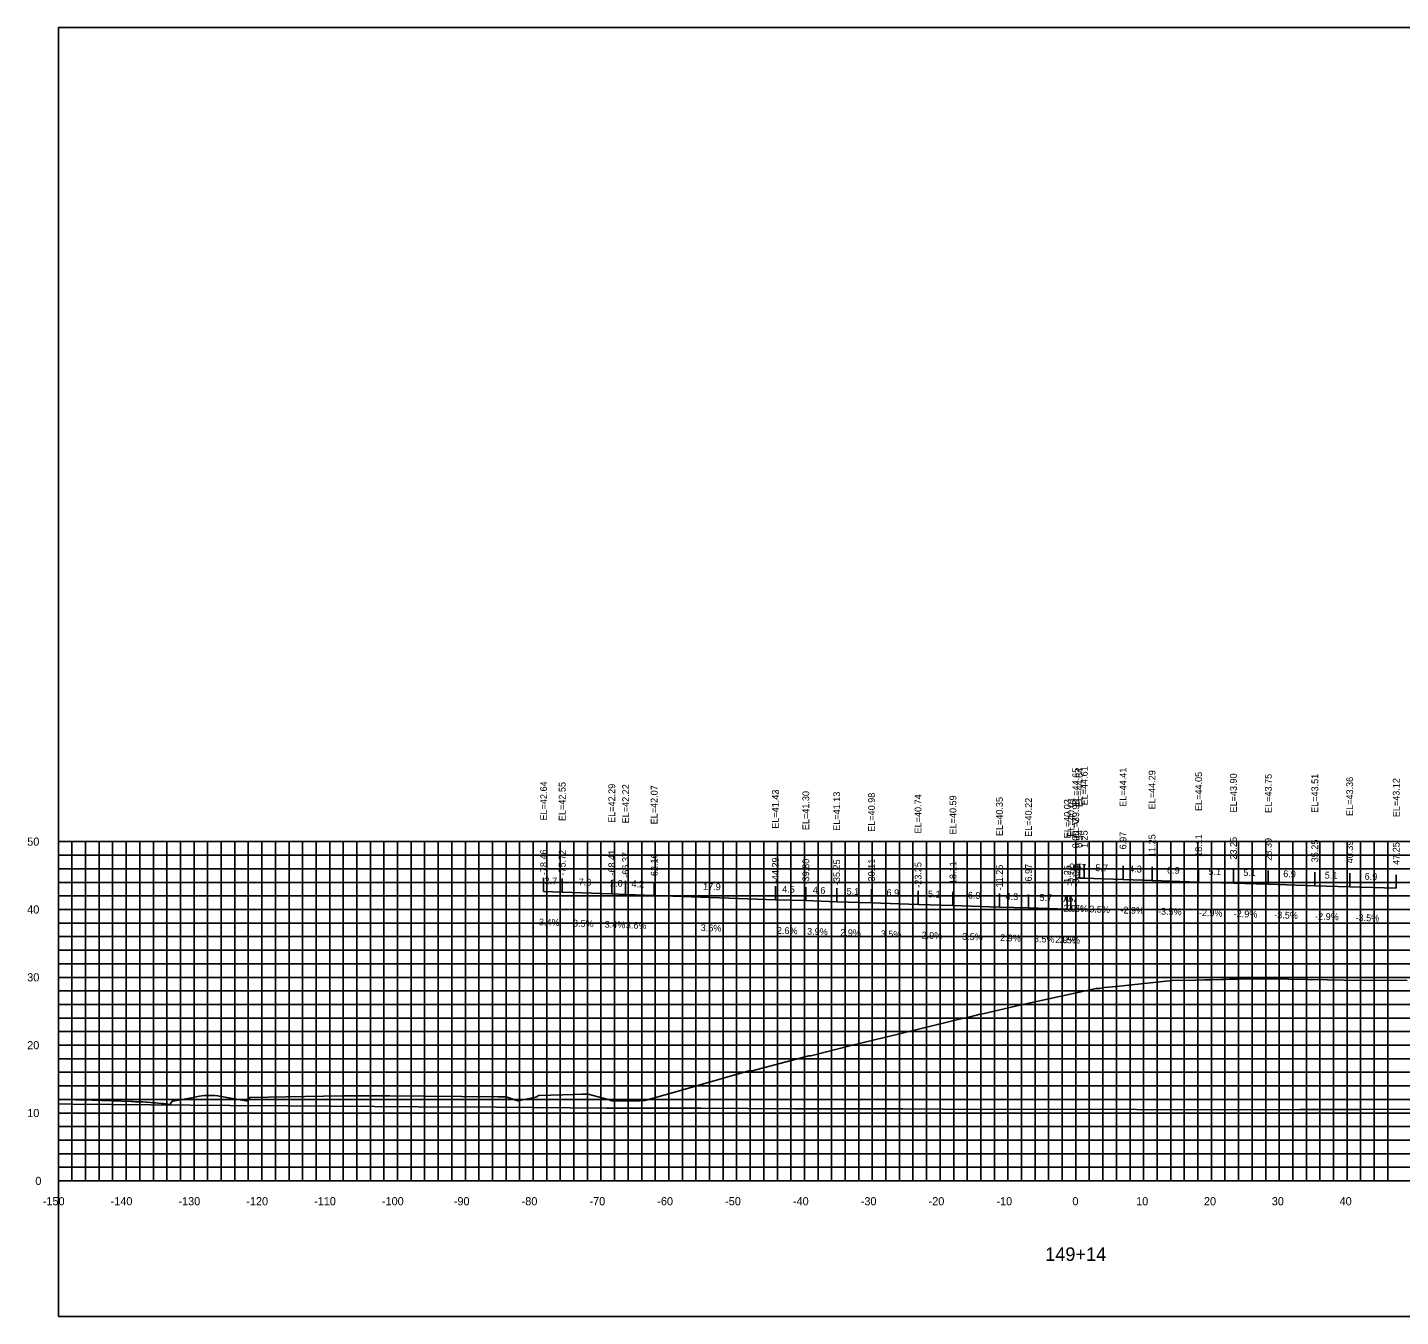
# Model space of a CAD drawing. Extents: x 1800880 to 1818864, y 245271 to 250560.
# Drawn here: x 1810016.6 to 1810219, y 249144.9 to 249334.9 of the extents above; entities that cross this region are included whole.
import ezdxf

# ---------------------------------------------------------------- set-up
doc = ezdxf.new("R2010")
doc.units = 0
for name, color, linetype in [('33', 7, 'Continuous'), ('ANNO-TXT', 7, 'Continuous'), ('AXIS', 7, 'Continuous'), ('CL-CNST', 7, 'Continuous'), ('DESIGN - DRAINAGE - Bridges', 7, 'Continuous'), ('Level 32', 7, 'Continuous'), ('Level 37', 7, 'Continuous'), ('Level 46', 7, 'Continuous'), ('Level 62', 7, 'Continuous'), ('SHT-BDR', 7, 'Continuous')]:
    doc.layers.add(name, color=color, linetype=linetype)

msp = doc.modelspace()

# ---------------------------------------------------------------- linework, layer by layer
at = {"layer": 'AXIS'}
msp.add_lwpolyline([(1810171.13, 249209.56), (1810171.67, 249209.54), (1810172.38, 249209.52), (1810178.1, 249209.32), (1810182.38, 249209.19), (1810189.25, 249208.95), (1810194.38, 249208.8), (1810199.52, 249208.65), (1810206.38, 249208.41), (1810211.52, 249208.26), (1810218.38, 249208.02)], dxfattribs=at)
at = {"layer": 'CL-CNST'}
msp.add_lwpolyline([(1810021.13, 249176.87), (1810026.09, 249176.8), (1810031.88, 249176.59), (1810032.15, 249176.58), (1810032.44, 249176.57), (1810032.77, 249176.56), (1810033.13, 249176.55), (1810033.54, 249176.53), (1810034, 249176.52), (1810034.22, 249176.51), (1810035.25, 249176.39), (1810035.47, 249176.39), (1810036.28, 249176.31), (1810036.63, 249176.28), (1810037.55, 249176.18), (1810037.6, 249176.18), (1810037.65, 249176.12), (1810037.68, 249176.29), (1810037.91, 249176.66), (1810038.02, 249176.66), (1810040.73, 249177.15), (1810041.91, 249177.37), (1810042.61, 249177.47), (1810042.7, 249177.48), (1810042.92, 249177.48), (1810043.49, 249177.49), (1810043.68, 249177.5), (1810043.88, 249177.5), (1810044.01, 249177.5), (1810044.19, 249177.5), (1810044.59, 249177.44), (1810049.07, 249176.65), (1810049.18, 249176.89), (1810049.26, 249177.06), (1810049.34, 249177.2), (1810054.69, 249177.3), (1810062.99, 249177.44), (1810070.01, 249177.41), (1810075.25, 249177.4), (1810085.99, 249177.29), (1810087.25, 249177.28), (1810087.29, 249177.26), (1810088.89, 249176.71), (1810091.52, 249177.22), (1810091.98, 249177.47), (1810091.98, 249177.47), (1810097.26, 249177.65), (1810098.3, 249177.69), (1810098.72, 249177.7), (1810099.2, 249177.7), (1810099.24, 249177.7), (1810102.21, 249176.89), (1810102.72, 249176.71), (1810102.78, 249176.71), (1810103.22, 249176.7), (1810103.74, 249176.69), (1810103.87, 249176.69), (1810106.83, 249176.68), (1810107.4, 249176.76), (1810107.6, 249176.76), (1810111.49, 249177.83), (1810122.95, 249181.12), (1810123.16, 249181.12), (1810123.42, 249181.12), (1810131.79, 249183.32), (1810132.09, 249183.33), (1810138.03, 249184.83), (1810142.9, 249186.04), (1810143.12, 249186.09), (1810154.58, 249188.87), (1810154.82, 249188.88), (1810157.02, 249189.49), (1810157.41, 249189.51), (1810162.88, 249190.79), (1810174.12, 249193.25), (1810174.16, 249193.25), (1810174.64, 249193.25), (1810175.37, 249193.39), (1810177.07, 249193.54), (1810179.38, 249193.78), (1810185.33, 249194.41), (1810188.78, 249194.5), (1810190.15, 249194.53), (1810190.59, 249194.55), (1810191.08, 249194.55), (1810192.68, 249194.59), (1810193.15, 249194.6), (1810193.78, 249194.62), (1810195.17, 249194.65), (1810197.09, 249194.7), (1810199.54, 249194.66), (1810208.26, 249194.53), (1810210.69, 249194.5), (1810219.98, 249194.41)], dxfattribs=at)
at = {"layer": 'DESIGN - DRAINAGE - Bridges'}
for p, q in [((1810021.07, 249214.9), (1810021.13, 249214.9)), ((1810021.13, 249164.9), (1810021.13, 249214.9)), ((1810021.07, 249204.9), (1810021.13, 249204.9)), ((1810021.07, 249194.9), (1810021.13, 249194.9)), ((1810021.07, 249184.9), (1810021.13, 249184.9)), ((1810021.07, 249174.9), (1810021.13, 249174.9)), ((1810021.07, 249164.9), (1810021.13, 249164.9)), ((1810021.13, 249164.9), (1810321.13, 249164.9)), ((1810021.13, 249164.84), (1810021.13, 249164.9)), ((1810031.13, 249164.84), (1810031.13, 249164.9)), ((1810041.13, 249164.84), (1810041.13, 249164.9)), ((1810051.13, 249164.84), (1810051.13, 249164.9)), ((1810061.13, 249164.84), (1810061.13, 249164.9)), ((1810071.13, 249164.84), (1810071.13, 249164.9)), ((1810081.13, 249164.84), (1810081.13, 249164.9)), ((1810091.13, 249164.84), (1810091.13, 249164.9)), ((1810101.13, 249164.84), (1810101.13, 249164.9)), ((1810111.13, 249164.84), (1810111.13, 249164.9)), ((1810121.13, 249164.84), (1810121.13, 249164.9)), ((1810131.13, 249164.84), (1810131.13, 249164.9)), ((1810141.13, 249164.84), (1810141.13, 249164.9)), ((1810151.13, 249164.84), (1810151.13, 249164.9)), ((1810161.13, 249164.84), (1810161.13, 249164.9)), ((1810171.13, 249164.84), (1810171.13, 249164.9)), ((1810181.13, 249164.84), (1810181.13, 249164.9)), ((1810191.13, 249164.84), (1810191.13, 249164.9)), ((1810201.13, 249164.84), (1810201.13, 249164.9)), ((1810211.13, 249164.84), (1810211.13, 249164.9))]:
    msp.add_line(p, q, dxfattribs=at)
at = {"layer": 'Level 37'}
for p, q in [((1810171.13, 249209.56), (1810171.13, 249211.56)), ((1810171.67, 249209.54), (1810171.67, 249211.54)), ((1810172.38, 249209.52), (1810172.38, 249211.52)), ((1810178.1, 249209.32), (1810178.1, 249211.32)), ((1810182.38, 249209.19), (1810182.38, 249211.19)), ((1810189.25, 249208.95), (1810189.25, 249210.95)), ((1810194.38, 249208.8), (1810194.38, 249210.8)), ((1810199.52, 249208.65), (1810199.52, 249210.65)), ((1810206.38, 249208.41), (1810206.38, 249210.41)), ((1810211.52, 249208.26), (1810211.52, 249210.26)), ((1810092.67, 249207.55), (1810092.67, 249209.55)), ((1810095.41, 249207.45), (1810095.41, 249209.45)), ((1810102.72, 249207.2), (1810102.72, 249209.2)), ((1810104.76, 249207.13), (1810104.76, 249209.13)), ((1810108.97, 249206.98), (1810108.97, 249208.98)), ((1810126.84, 249206.33), (1810126.84, 249208.33)), ((1810126.84, 249206.32), (1810126.84, 249208.32)), ((1810131.33, 249206.21), (1810131.33, 249208.21)), ((1810135.88, 249206.03), (1810135.88, 249208.03)), ((1810218.38, 249208.02), (1810218.38, 249210.02)), ((1810141.02, 249205.88), (1810141.02, 249207.88)), ((1810147.88, 249205.64), (1810147.88, 249207.64)), ((1810153.02, 249205.49), (1810153.02, 249207.49)), ((1810159.88, 249205.25), (1810159.88, 249207.25)), ((1810164.16, 249205.13), (1810164.16, 249207.13)), ((1810169.88, 249204.93), (1810169.88, 249206.93)), ((1810170.42, 249204.91), (1810170.42, 249206.91)), ((1810171.13, 249204.89), (1810171.13, 249206.89))]:
    msp.add_line(p, q, dxfattribs=at)
msp.add_lwpolyline([(1810021.13, 249144.9), (1810321.13, 249144.9), (1810321.13, 249334.9), (1810021.13, 249334.9)], close=True, dxfattribs=at)
at = {"layer": 'Level 46'}
for p, q in [((1810021.13, 249214.9), (1810321.13, 249214.9)), ((1810021.13, 249164.9), (1810021.13, 249214.9)), ((1810023.13, 249164.9), (1810023.13, 249214.9)), ((1810025.13, 249164.9), (1810025.13, 249214.9)), ((1810027.13, 249164.9), (1810027.13, 249214.9)), ((1810029.13, 249164.9), (1810029.13, 249214.9)), ((1810031.13, 249164.9), (1810031.13, 249214.9)), ((1810033.13, 249164.9), (1810033.13, 249214.9)), ((1810035.13, 249164.9), (1810035.13, 249214.9)), ((1810037.13, 249164.9), (1810037.13, 249214.9)), ((1810039.13, 249164.9), (1810039.13, 249214.9)), ((1810041.13, 249164.9), (1810041.13, 249214.9)), ((1810043.13, 249164.9), (1810043.13, 249214.9)), ((1810045.13, 249164.9), (1810045.13, 249214.9)), ((1810047.13, 249164.9), (1810047.13, 249214.9)), ((1810049.13, 249164.9), (1810049.13, 249214.9)), ((1810051.13, 249164.9), (1810051.13, 249214.9)), ((1810053.13, 249164.9), (1810053.13, 249214.9)), ((1810055.13, 249164.9), (1810055.13, 249214.9)), ((1810057.13, 249164.9), (1810057.13, 249214.9)), ((1810059.13, 249164.9), (1810059.13, 249214.9)), ((1810061.13, 249164.9), (1810061.13, 249214.9)), ((1810063.13, 249164.9), (1810063.13, 249214.9)), ((1810065.13, 249164.9), (1810065.13, 249214.9)), ((1810067.13, 249164.9), (1810067.13, 249214.9)), ((1810069.13, 249164.9), (1810069.13, 249214.9)), ((1810071.13, 249164.9), (1810071.13, 249214.9)), ((1810073.13, 249164.9), (1810073.13, 249214.9)), ((1810075.13, 249164.9), (1810075.13, 249214.9)), ((1810077.13, 249164.9), (1810077.13, 249214.9)), ((1810079.13, 249164.9), (1810079.13, 249214.9)), ((1810081.13, 249164.9), (1810081.13, 249214.9)), ((1810083.13, 249164.9), (1810083.13, 249214.9)), ((1810085.13, 249164.9), (1810085.13, 249214.9)), ((1810087.13, 249164.9), (1810087.13, 249214.9)), ((1810089.13, 249164.9), (1810089.13, 249214.9)), ((1810091.13, 249164.9), (1810091.13, 249214.9)), ((1810093.13, 249164.9), (1810093.13, 249214.9)), ((1810095.13, 249164.9), (1810095.13, 249214.9)), ((1810097.13, 249164.9), (1810097.13, 249214.9)), ((1810099.13, 249164.9), (1810099.13, 249214.9)), ((1810101.13, 249164.9), (1810101.13, 249214.9)), ((1810103.13, 249164.9), (1810103.13, 249214.9)), ((1810105.13, 249164.9), (1810105.13, 249214.9)), ((1810107.13, 249164.9), (1810107.13, 249214.9)), ((1810109.13, 249164.9), (1810109.13, 249214.9)), ((1810111.13, 249164.9), (1810111.13, 249214.9)), ((1810113.13, 249164.9), (1810113.13, 249214.9)), ((1810115.13, 249164.9), (1810115.13, 249214.9)), ((1810117.13, 249164.9), (1810117.13, 249214.9)), ((1810119.13, 249164.9), (1810119.13, 249214.9)), ((1810121.13, 249164.9), (1810121.13, 249214.9)), ((1810123.13, 249164.9), (1810123.13, 249214.9)), ((1810125.13, 249164.9), (1810125.13, 249214.9)), ((1810127.13, 249164.9), (1810127.13, 249214.9)), ((1810129.13, 249164.9), (1810129.13, 249214.9)), ((1810131.13, 249164.9), (1810131.13, 249214.9)), ((1810133.13, 249164.9), (1810133.13, 249214.9)), ((1810135.13, 249164.9), (1810135.13, 249214.9)), ((1810137.13, 249164.9), (1810137.13, 249214.9)), ((1810139.13, 249164.9), (1810139.13, 249214.9)), ((1810141.13, 249164.9), (1810141.13, 249214.9)), ((1810143.13, 249164.9), (1810143.13, 249214.9)), ((1810145.13, 249164.9), (1810145.13, 249214.9)), ((1810147.13, 249164.9), (1810147.13, 249214.9)), ((1810149.13, 249164.9), (1810149.13, 249214.9)), ((1810151.13, 249164.9), (1810151.13, 249214.9)), ((1810153.13, 249164.9), (1810153.13, 249214.9)), ((1810155.13, 249164.9), (1810155.13, 249214.9)), ((1810157.13, 249164.9), (1810157.13, 249214.9)), ((1810159.13, 249164.9), (1810159.13, 249214.9)), ((1810161.13, 249164.9), (1810161.13, 249214.9)), ((1810163.13, 249164.9), (1810163.13, 249214.9)), ((1810165.13, 249164.9), (1810165.13, 249214.9)), ((1810167.13, 249164.9), (1810167.13, 249214.9)), ((1810169.13, 249164.9), (1810169.13, 249214.9)), ((1810171.13, 249164.9), (1810171.13, 249214.9)), ((1810173.13, 249164.9), (1810173.13, 249214.9)), ((1810175.13, 249164.9), (1810175.13, 249214.9)), ((1810177.13, 249164.9), (1810177.13, 249214.9)), ((1810179.13, 249164.9), (1810179.13, 249214.9)), ((1810181.13, 249164.9), (1810181.13, 249214.9)), ((1810183.13, 249164.9), (1810183.13, 249214.9)), ((1810185.13, 249164.9), (1810185.13, 249214.9)), ((1810187.13, 249164.9), (1810187.13, 249214.9)), ((1810189.13, 249164.9), (1810189.13, 249214.9)), ((1810191.13, 249164.9), (1810191.13, 249214.9)), ((1810193.13, 249164.9), (1810193.13, 249214.9)), ((1810195.13, 249164.9), (1810195.13, 249214.9)), ((1810197.13, 249164.9), (1810197.13, 249214.9)), ((1810199.13, 249164.9), (1810199.13, 249214.9)), ((1810201.13, 249164.9), (1810201.13, 249214.9)), ((1810203.13, 249164.9), (1810203.13, 249214.9)), ((1810205.13, 249164.9), (1810205.13, 249214.9)), ((1810207.13, 249164.9), (1810207.13, 249214.9)), ((1810209.13, 249164.9), (1810209.13, 249214.9)), ((1810211.13, 249164.9), (1810211.13, 249214.9)), ((1810213.13, 249164.9), (1810213.13, 249214.9)), ((1810215.13, 249164.9), (1810215.13, 249214.9)), ((1810217.13, 249164.9), (1810217.13, 249214.9)), ((1810021.13, 249212.9), (1810321.13, 249212.9)), ((1810021.13, 249210.9), (1810321.13, 249210.9)), ((1810021.13, 249208.9), (1810321.13, 249208.9)), ((1810021.13, 249206.9), (1810321.13, 249206.9)), ((1810021.13, 249204.9), (1810321.13, 249204.9)), ((1810021.13, 249202.9), (1810321.13, 249202.9)), ((1810021.13, 249200.9), (1810321.13, 249200.9)), ((1810021.13, 249198.9), (1810321.13, 249198.9)), ((1810021.13, 249196.9), (1810321.13, 249196.9)), ((1810021.13, 249194.9), (1810321.13, 249194.9)), ((1810021.13, 249192.9), (1810321.13, 249192.9)), ((1810021.13, 249190.9), (1810321.13, 249190.9)), ((1810021.13, 249188.9), (1810321.13, 249188.9)), ((1810021.13, 249186.9), (1810321.13, 249186.9)), ((1810021.13, 249184.9), (1810321.13, 249184.9)), ((1810021.13, 249182.9), (1810321.13, 249182.9)), ((1810021.13, 249180.9), (1810321.13, 249180.9)), ((1810021.13, 249178.9), (1810321.13, 249178.9)), ((1810021.13, 249176.9), (1810321.13, 249176.9)), ((1810021.13, 249174.9), (1810321.13, 249174.9)), ((1810021.13, 249172.9), (1810321.13, 249172.9)), ((1810021.13, 249170.9), (1810321.13, 249170.9)), ((1810021.13, 249168.9), (1810321.13, 249168.9)), ((1810021.13, 249166.9), (1810321.13, 249166.9)), ((1810021.13, 249164.9), (1810321.13, 249164.9))]:
    msp.add_line(p, q, dxfattribs=at)
at = {"layer": 'Level 62'}
for points in [[(1810092.67, 249207.55), (1810095.41, 249207.45), (1810102.72, 249207.2), (1810104.76, 249207.13), (1810108.97, 249206.98), (1810126.84, 249206.33)], [(1810126.84, 249206.32), (1810131.33, 249206.21), (1810135.88, 249206.03), (1810141.02, 249205.88), (1810147.88, 249205.64), (1810153.02, 249205.49), (1810159.88, 249205.25), (1810164.16, 249205.13), (1810169.88, 249204.93), (1810170.42, 249204.91), (1810171.13, 249204.89)], [(1810021.13, 249176.24), (1810023.09, 249176.23), (1810046.41, 249176), (1810054.86, 249175.96), (1810074.17, 249175.81), (1810085.71, 249175.78), (1810101.92, 249175.63), (1810115.9, 249175.6), (1810129.68, 249175.51), (1810145.64, 249175.51), (1810157.43, 249175.43), (1810175.04, 249175.46), (1810185.19, 249175.38), (1810204.17, 249175.44), (1810212.94, 249175.42), (1810233.1, 249175.51), (1810240.7, 249175.52), (1810261.87, 249175.64), (1810268.46, 249175.52), (1810290.52, 249175.66), (1810296.21, 249175.72), (1810301.46, 249175.68), (1810321.13, 249175.8)]]:
    msp.add_lwpolyline(points, dxfattribs=at)

# ---------------------------------------------------------------- texts
for s, p in [('-150', (1810018.83, 249161.3)), ('-140', (1810028.83, 249161.3)), ('-130', (1810038.83, 249161.3)), ('-120', (1810048.83, 249161.3)), ('-110', (1810058.83, 249161.3)), ('-100', (1810068.83, 249161.3)), ('-90', (1810079.43, 249161.3)), ('-80', (1810089.43, 249161.3)), ('-70', (1810099.43, 249161.3)), ('-60', (1810109.43, 249161.3)), ('-50', (1810119.43, 249161.3)), ('-40', (1810129.43, 249161.3)), ('-30', (1810139.43, 249161.3)), ('-20', (1810149.43, 249161.3)), ('-10', (1810159.43, 249161.3)), ('0', (1810170.63, 249161.3)), ('10', (1810180.03, 249161.3)), ('20', (1810190.03, 249161.3)), ('30', (1810200.03, 249161.3)), ('40', (1810210.03, 249161.3))]:
    msp.add_text(s, height=1.2).set_placement(p)
at = {"layer": '33'}
for s, p in [('50', (1810016.53, 249214.3)), ('40', (1810016.53, 249204.3)), ('30', (1810016.53, 249194.3)), ('20', (1810016.53, 249184.3)), ('10', (1810016.53, 249174.3)), ('0', (1810017.73, 249164.3))]:
    msp.add_text(s, height=1.2, dxfattribs=at).set_placement(p)
at = {"layer": 'ANNO-TXT'}
for s, rotation, p in [('0.5', 358.3363, (1810170.15, 249210.69)), ('0.7', 357.9961, (1810170.78, 249210.67)), ('5.7', 357.9961, (1810174, 249210.56)), ('4.3', 358.3363, (1810178.99, 249210.39)), ('6.9', 357.9961, (1810184.57, 249210.22)), ('5.1', 358.3363, (1810190.69, 249210.01)), ('5.1', 358.3363, (1810195.83, 249209.86)), ('6.9', 357.9961, (1810201.71, 249209.68)), ('5.1', 358.3363, (1810207.83, 249209.47)), ('6.9', 357.9961, (1810213.71, 249209.29)), ('2.7', 358.0395, (1810092.79, 249208.64)), ('7.3', 357.9753, (1810097.82, 249208.47)), ('2.0', 358.0287, (1810102.46, 249208.31)), ('4.2', 357.9495, (1810105.62, 249208.2)), ('17.9', 357.9451, (1810116.17, 249207.82)), ('4.5', 358.5361, (1810127.83, 249207.4)), ('4.6', 357.7742, (1810132.34, 249207.27)), ('5.1', 358.3363, (1810137.33, 249207.09)), ('6.9', 357.9961, (1810143.21, 249206.91)), ('5.1', 358.3363, (1810149.33, 249206.7)), ('6.9', 357.9961, (1810155.21, 249206.52)), ('4.3', 358.3363, (1810160.77, 249206.33)), ('5.7', 357.9961, (1810165.78, 249206.17)), ('0.5', 358.3363, (1810168.9, 249206.06)), ('0.7', 357.9961, (1810169.53, 249206.04)), ('-2.9%', 358.3363, (1810168.85, 249204.62)), ('-3.5%', 357.9961, (1810169.44, 249204.62)), ('-3.5%', 357.9961, (1810172.66, 249204.5)), ('-2.9%', 358.3363, (1810177.69, 249204.33)), ('-3.5%', 357.9961, (1810183.23, 249204.16)), ('-2.9%', 358.3363, (1810189.26, 249203.95)), ('-2.9%', 358.3363, (1810194.4, 249203.8)), ('-3.5%', 357.9961, (1810200.37, 249203.62)), ('-2.9%', 358.3363, (1810206.4, 249203.41)), ('-3.5%', 357.9961, (1810212.37, 249203.23)), ('3.4%', 358.0395, (1810091.96, 249202.57)), ('3.5%', 357.9753, (1810096.98, 249202.4)), ('3.4%', 358.0287, (1810101.66, 249202.23)), ('3.6%', 357.9495, (1810104.78, 249202.12)), ('3.6%', 357.9451, (1810115.82, 249201.73)), ('2.6%', 358.5361, (1810127.05, 249201.32)), ('3.9%', 357.7742, (1810131.5, 249201.2)), ('2.9%', 358.3363, (1810136.39, 249201.01)), ('3.5%', 357.9961, (1810142.36, 249200.83)), ('2.9%', 358.3363, (1810148.39, 249200.62)), ('3.5%', 357.9961, (1810154.36, 249200.44)), ('2.9%', 358.3363, (1810159.97, 249200.25)), ('3.5%', 357.9961, (1810164.94, 249200.1)), ('2.9%', 358.3363, (1810168.09, 249199.98)), ('3.5%', 357.9961, (1810168.69, 249199.97))]:
    msp.add_text(s, height=1, rotation=rotation, dxfattribs=at).set_placement(p)
at = {"layer": 'DESIGN - DRAINAGE - Bridges'}
for s, height, p in [('>', 1.5, (1810170.52, 249217.15)), ('-', 0.0001, (1810021.13, 249164.9))]:
    msp.add_text(s, height=height, dxfattribs=at).set_placement(p)
at = {"layer": 'Level 32'}
msp.add_text('149+14', height=2, dxfattribs=at).set_placement((1810166.62, 249153.1))
at = {"layer": 'SHT-BDR'}
for s, p in [('EL=44.65', (1810171.63, 249220.03)), ('EL=44.64', (1810172.17, 249220.01)), ('EL=44.61', (1810172.88, 249220.24)), ('EL=44.41', (1810178.6, 249220.04)), ('EL=44.29', (1810182.88, 249219.66)), ('EL=44.05', (1810189.75, 249219.42)), ('EL=43.90', (1810194.88, 249219.2)), ('EL=43.75', (1810200.02, 249219.13)), ('EL=43.51', (1810206.88, 249219.14)), ('EL=43.36', (1810212.02, 249218.69)), ('EL=42.64', (1810093.17, 249218.02)), ('EL=42.55', (1810095.91, 249217.93)), ('EL=42.29', (1810103.22, 249217.67)), ('EL=42.22', (1810105.26, 249217.6)), ('EL=42.07', (1810109.47, 249217.45)), ('EL=41.43', (1810127.34, 249216.81)), ('EL=41.42', (1810127.34, 249216.79)), ('EL=41.30', (1810131.83, 249216.6)), ('EL=41.13', (1810136.38, 249216.5)), ('EL=43.12', (1810218.88, 249218.5)), ('EL=40.98', (1810141.52, 249216.35)), ('EL=40.74', (1810148.38, 249216.11)), ('EL=40.59', (1810153.52, 249215.96)), ('EL=40.35', (1810160.38, 249215.72)), ('EL=40.22', (1810164.66, 249215.6)), ('EL=40.02', (1810170.38, 249215.4)), ('EL=40.01', (1810170.92, 249215.64)), ('EL=39.98', (1810171.63, 249215.36)), ('0.00', (1810171.63, 249213.92)), ('0.54', (1810172.17, 249213.98)), ('1.25', (1810172.88, 249213.96)), ('6.97', (1810178.6, 249213.76)), ('11.25', (1810182.88, 249212.64)), ('18.11', (1810189.75, 249212.65)), ('23.25', (1810194.88, 249212.25)), ('28.39', (1810200.02, 249212.1)), ('35.25', (1810206.88, 249211.86)), ('40.39', (1810212.02, 249211.71)), ('47.25', (1810218.88, 249211.47)), ('-78.46', (1810093.17, 249209.96)), ('-75.72', (1810095.91, 249209.91)), ('-68.41', (1810103.22, 249209.9)), ('-66.37', (1810105.26, 249209.58)), ('-62.16', (1810109.47, 249209.38)), ('-44.29', (1810127.34, 249208.79)), ('-44.29', (1810127.34, 249208.78)), ('-39.80', (1810131.83, 249208.59)), ('-35.25', (1810136.38, 249208.49)), ('-30.11', (1810141.52, 249208.59)), ('-23.25', (1810148.38, 249208.1)), ('-18.11', (1810153.52, 249208.2)), ('-11.25', (1810160.38, 249207.71)), ('-6.97', (1810164.66, 249208.58)), ('-1.25', (1810170.38, 249208.38)), ('-0.72', (1810170.92, 249208.36)), ('-0.00', (1810171.63, 249208.26))]:
    msp.add_text(s, height=1, rotation=90, dxfattribs=at).set_placement(p)

doc.saveas('drawing.dxf')
